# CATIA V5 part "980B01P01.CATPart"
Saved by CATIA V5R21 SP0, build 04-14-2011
Part number: 980B01P01
Bounding box of the stored display mesh (mm): x -33.4 to 33.4, y -100 to 100, z -8 to 8
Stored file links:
  C:\Users\ALI OZGUN\Desktop\alhan\980B01P01.CATPart
  C:\Users\ALI OZGUN\Desktop\alhan\943B01P01.CATPart
  C:\Users\ALI OZGUN\Desktop\alhan\950B01P01.CATPart
  C:\Users\ALI OZGUN\Desktop\alhan\Product1.CATProduct
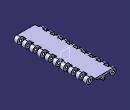
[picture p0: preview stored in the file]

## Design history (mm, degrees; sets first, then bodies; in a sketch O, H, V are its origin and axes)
Body1 (main body)
Body2
  Sketch1 on zx-plane, origin (0, 0, 0), H (-1, 0, 0), V (0, 0, 1)
    construction line L1 (25.4, 8) -> (25.4, -8)
    line L2 (25.4, -8) -> (-25.4, -8)
    construction line L3 (-25.4, -8) -> (-25.4, 8)
    line L4 (-25.4, 8) -> (25.4, 8)
    point P3 (-25.4, -8)
    arc A1 centre (25.4, 0) radius 8 from (25.4, 8) to (25.4, -8) cw
    arc A2 centre (-25.4, 0) radius 8 from (-25.4, 8) to (-25.4, -8) ccw
    point P7 (-25.4, -8)
    length L4 = 50.8
    length L3 = 16
    vertical: L1 V, L3 V
    horizontal: L2 H, L4 H
    equidistance: L1 L3 O, L2 L4 O
    tangency: A1 L2, A2 L4, A2 L2, L4 A1
    coincidence: P7 L2, P3 P7
  Pad1: profile Sketch1, direction (0, 1, 0), length 100, mirrored extent
  Sketch2 on zx-plane, origin (0, 0, 0), H (-1, 0, 0), V (0, 0, 1)
    circle A1 centre (25.4, 0) radius 3.15
    circle A2 centre (-25.4, 0) radius 3.15
  Pocket1: profile Sketch2, direction (0, -1, 0), length 204, mirrored extent
  Body3 "aramesefa"
    Sketch3 on face of Pad1 from Sketch1.L4, origin (0, 0, 8), H (1, 0, 0), V (0, 1, 0)
      line L1 (21.5, -80) -> (55.8232, -80)
      line L2 (55.8232, -80) -> (55.8232, -90.5)
      line L3 (55.8232, -90.5) -> (21.5, -90.5)
      line L4 (21.5, -90.5) -> (21.5, -80)
      reference projected line E1 (-25.4, -100) -> (25.4, -100) from edge [start face of Pad1 | face of Pad1 from Sketch1.L4]
      line L5 (-54.1233, -90) -> (-21.5, -90)
      line L6 (-21.5, -90) -> (-21.5, -100.5)
      line L7 (-21.5, -100.5) -> (-54.1233, -100.5)
      line L8 (-54.1233, -100.5) -> (-54.1233, -90)
      reference projected line E2 (-25.4, -100) -> (25.4, -100) from edge [start face of Pad1 | face of Pad1 from Sketch1.L4]
      distance L1 L3 = 10.5
      distance L3 E1 = 9.5
      distance L4 V = 21.5
      distance L5 L3 = 0.5
      distance L7 E2 = 0.5
      distance L6 L4 = 43
      horizontal: L1 H, L3 H, L5 H, L7 H
      vertical: L2 V, L4 V, L6 V, L8 V
    Pad2: profile Sketch3, direction (0, 0, 1), length 20, mirrored extent
    RectPattern1: of the body so far, direction 1 instances 10, spacing 20, along yz-plane
  Remove1: tool Body3
  Body4 "ALTBOSLUK"
    Sketch4 on zx-plane, origin (0, 0, 0), H (-1, 0, 0), V (0, 0, 1)
      line L1 (48.9583, 0) -> (33.4, 0)
      arc A1 centre (25.4, 0) radius 8 from (17.4, 0) to (33.4, 0) ccw
      line L2 (17.4, 0) -> (17.4, 0.2)
      arc A2 centre (15.4, 0.2) radius 2 from (17.4, 0.2) to (15.4, 2.2) ccw
      line L3 (15.4, 2.2) -> (5.5215, 2.2)
      arc A3 centre (5.5215, 0.2) radius 2 from (5.5215, 2.2) to (3.5325, 0.4091) ccw
      line L4 (3.5325, 0.4091) -> (2.9836, -4.8136)
      arc A4 centre (0, -4.4996) radius 3 from (-2.9836, -4.8136) to (2.9836, -4.8136) ccw
      line L5 (-2.9836, -4.8136) -> (-3.5325, 0.4091)
      arc A5 centre (-5.5215, 0.2) radius 2 from (-3.5325, 0.4091) to (-5.5215, 2.2) ccw
      line L6 (-5.5215, 2.2) -> (-15.4, 2.2)
      arc A6 centre (-15.4, 0.2) radius 2 from (-15.4, 2.2) to (-17.4, 0.2) ccw
      line L7 (-17.4, 0.2) -> (-17.4, 0)
      arc A7 centre (-25.4, 0) radius 8 from (-33.4, 0) to (-17.4, 0) ccw
      line L8 (-33.4, 0) -> (-46.3888, 0)
      line L9 (-46.3888, 0) -> (-46.3888, -17.807)
      line L10 (-46.3888, -17.807) -> (48.9583, -17.807)
      line L11 (48.9583, -17.807) -> (48.9583, 0)
      vertical: L9 V, L11 V
      horizontal: L10 H
    Pad3: profile Sketch4, direction (0, 1, 0), length 215, mirrored extent
  Remove2: tool Body4
  Body5 "KALANTIBOSALTMA"
    Sketch5 on face of Pad1 from Sketch1.L4, origin (0, 0, 8), H (1, 0, 0), V (0, 1, 0)
      line L1 (10, -80) -> (55.8232, -80)
      line L2 (55.8232, -80) -> (55.8232, -90.5)
      line L3 (55.8232, -90.5) -> (10, -90.5)
      line L4 (10, -90.5) -> (10, -80)
      reference projected line E1 (-25.4, -100) -> (25.4, -100) from edge [start face of Pad1 | face of Pad1 from Sketch1.L4]
      line L5 (-54.1233, -90) -> (-10, -90)
      line L6 (-10, -90) -> (-10, -100.5)
      line L7 (-10, -100.5) -> (-54.1233, -100.5)
      line L8 (-54.1233, -100.5) -> (-54.1233, -90)
      reference projected line E2 (-25.4, -100) -> (25.4, -100) from edge [start face of Pad1 | face of Pad1 from Sketch1.L4]
      distance L1 L3 = 10.5
      distance L3 E1 = 9.5
      distance L4 V = 10
      distance L5 L3 = 0.5
      distance L7 E2 = 0.5
      distance L6 L4 = 20
      horizontal: L1 H, L3 H, L5 H, L7 H
      vertical: L2 V, L4 V, L6 V, L8 V
    Pad4: profile Sketch5, direction (0, 0, 1), length 20, mirrored extent
    RectPattern2: of the body so far, direction 1 instances 10, spacing 20, along yz-plane
    Sketch6 on zx-plane, origin (0, 0, 0), H (-1, 0, 0), V (0, 0, 1)
      line L1 (108.0577, 2.2) -> (-84.5523, 2.2)
      fix: L1
    Pocket2: profile Sketch6, direction (0, -1, 0), length 215, mirrored extent
  Remove3: tool Body5
  Body6 "aramesefa ACILARI"
    Sketch7 on face of Pad1 from Sketch1.L4, origin (0, 0, 8), H (1, 0, 0), V (0, 1, 0)
      line L1 (21.5, -80) -> (55.8232, -80)
      line L2 (55.8232, -80) -> (55.8232, -90.5)
      line L3 (55.8232, -90.5) -> (21.5, -90.5)
      line L4 (21.5, -90.5) -> (21.5, -80)
      reference projected line E1 (-25.4, -100) -> (25.4, -100) from edge [start face of Pad1 | face of Pad1 from Sketch1.L4]
      line L5 (-54.1233, -90) -> (-21.5, -90)
      line L6 (-21.5, -90) -> (-21.5, -100.5)
      line L7 (-21.5, -100.5) -> (-54.1233, -100.5)
      line L8 (-54.1233, -100.5) -> (-54.1233, -90)
      reference projected line E2 (-25.4, -100) -> (25.4, -100) from edge [start face of Pad1 | face of Pad1 from Sketch1.L4]
      distance L1 L3 = 10.5
      distance L3 E1 = 9.5
      distance L4 V = 21.5
      distance L5 L3 = 0.5
      distance L7 E2 = 0.5
      distance L6 L4 = 43
      horizontal: L1 H, L3 H, L5 H, L7 H
      vertical: L2 V, L4 V, L6 V, L8 V
    Pad5: profile Sketch7, direction (0, 0, 1), length 20, mirrored extent
    Sketch8 on zx-plane, origin (0, 0, 0), H (-1, 0, 0), V (0, 0, 1)
      line L1 (67.6223, 8) -> (-70.015, 8)
      fix: L1
    Pocket3: profile Sketch8, direction (0, -1, 0), length 215, mirrored extent
    Draft1: Angle 45, Neutral face of Pocket3 from Sketch8.L1, PullDir face of Pocket3 from Sketch8.L1, SupportToDraft face of Pad5 from Sketch7.L6
    Draft2: Angle 45, Neutral face of Pocket3 from Sketch8.L1, PullDir face of Pocket3 from Sketch8.L1, SupportToDraft face of Pad5 from Sketch7.L4
    RectPattern3: of the body so far, direction 1 instances 10, spacing 20, along yz-plane
  Remove4: tool Body6
  Sketch9 on zx-plane, origin (0, 0, 0), H (-1, 0, 0), V (0, 0, 1)
    line L1 (0, 72) -> (0, 6.9718)
    point P1 (0, 72)
    reference projected line E1 (-25.4, -8) -> (25.4, -8) from edge [face of Pad1 from Sketch1.L2 | end face of Pad1]
    distance P1 E1 = 80
    coincidence: P1 V
    vertical: L1 V
Body7
  Solid1: linked copy from another document
  Translate1: Direction yz-plane, ToTransfor Solid1, Length 50.8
